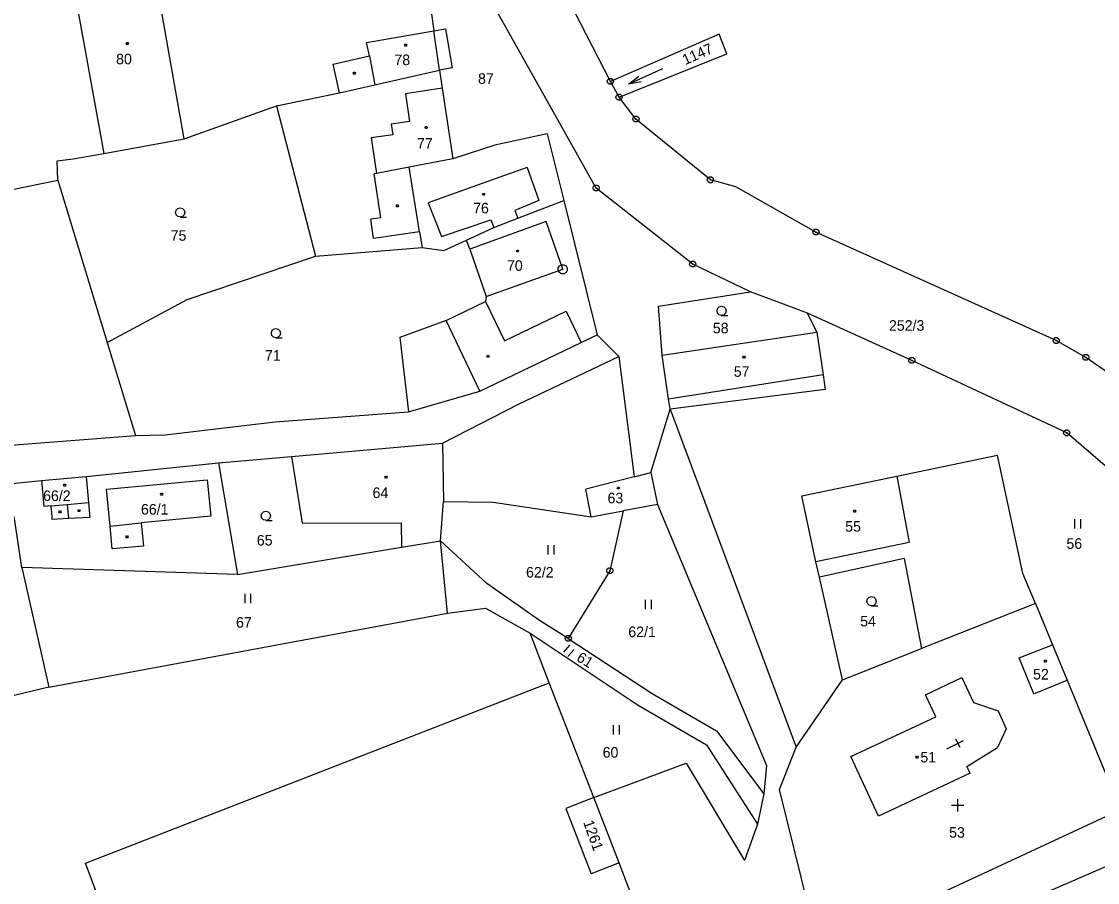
# Model space of a CAD drawing. Extents: x -812394 to -807601, y -1013098 to -1009266.
# Drawn here: x -809780.5 to -809607.5, y -1011042.4 to -1010903.9 of the extents above; entities that cross this region are included whole.
import ezdxf

# ---------------------------------------------------------------- set-up
doc = ezdxf.new("R2010")
doc.units = 0
for name, color, linetype in [('KN_HRANICE', 7, 'Continuous'), ('KN_KULTURY', 7, 'Continuous'), ('KN_MEZNIKY', 7, 'Continuous'), ('KN_PARCELY', 7, 'Continuous'), ('KN_SLUCKY', 7, 'Continuous')]:
    doc.layers.add(name, color=color, linetype=linetype)

# ---------------------------------------------------------------- blocks, each defined once
blk = doc.blocks.new('101')
blk.add_line((-0.05, 0), (0.05, 0))
blk.add_lwpolyline([(0.19, 0.72), (0.53, 0.53), (0.72, 0.19), (0.72, -0.2), (0.53, -0.54), (0.19, -0.73), (-0.2, -0.73), (-0.54, -0.54), (-0.73, -0.2), (-0.73, 0.19), (-0.54, 0.53), (-0.2, 0.72), (0.19, 0.72)])
blk = doc.blocks.new('304')
blk.add_lwpolyline([(0, 0), (-0.38, 0.1), (-0.65, 0.37), (-0.75, 0.74), (-0.65, 1.11), (-0.38, 1.38), (-0.01, 1.48), (0.36, 1.38), (0.63, 1.11), (0.73, 0.73), (0.63, 0.35), (0.36, 0.08), (-0.02, -0.02), (0.98, -0.02)])
blk = doc.blocks.new('306')
for p, q in [((-0.5, 1.5), (-0.5, 0)), ((0.5, 0), (0.5, 1.5))]:
    blk.add_line(p, q)
blk = doc.blocks.new('315')
for p, q in [((0, 0), (0, 2)), ((-1, 1), (1, 1))]:
    blk.add_line(p, q)
blk = doc.blocks.new('NAHRADNI_SYMBOL')
blk.add_lwpolyline([(0.09, 0.15), (0.18, 0), (0.09, -0.15), (-0.09, -0.15), (-0.18, 0), (-0.09, 0.15), (0.09, 0.15)])
blk = doc.blocks.new('802')
blk.add_line((-3, 0), (3, 0))
blk.add_lwpolyline([(1, 0.5), (3, 0), (1, -0.5)])
blk = doc.blocks.new('402')
blk.add_lwpolyline([(0.09, 0.15), (0.18, 0), (0.09, -0.15), (-0.09, -0.15), (-0.18, 0), (-0.09, 0.15), (0.09, 0.15)])
blk = doc.blocks.new('4091')
for p, q in [((0.75, 2), (-0.75, 2)), ((0, 0), (0, 3))]:
    blk.add_line(p, q)
blk = doc.blocks.new('105')
blk.add_line((-0.12, 0), (0.12, 0))
blk.add_lwpolyline([(0.15, 0.48), (0.4, 0.3), (0.5, 0.01), (0.4, -0.28), (0.15, -0.46), (-0.16, -0.46), (-0.41, -0.28), (-0.51, 0.01), (-0.41, 0.3), (-0.16, 0.48), (0.15, 0.48)])

msp = doc.modelspace()

# ---------------------------------------------------------------- linework, layer by layer
at = {"layer": 'KN_HRANICE'}
for p, q in [((-809754.39, -1010922.74), (-809759.51, -1010893.83)), ((-809772.62, -1010895.72), (-809767.28, -1010925.14)), ((-809715.33, -1010897.38), (-809714.24, -1010905.37)), ((-809688.11, -1010930.67), (-809707.45, -1010896.24)), ((-809685.82, -1010913.52), (-809691.58, -1010902.27)), ((-809725.07, -1010907.24), (-809714.24, -1010905.37)), ((-809714.24, -1010905.37), (-809712.36, -1010905.04)), ((-809712.36, -1010905.04), (-809711.25, -1010911.34)), ((-809724.57, -1010909.43), (-809725.07, -1010907.24)), ((-809730.42, -1010910.76), (-809724.57, -1010909.43)), ((-809729.38, -1010915.34), (-809730.42, -1010910.76)), ((-809723.69, -1010914.05), (-809713.3, -1010911.69)), ((-809711.25, -1010911.34), (-809713.3, -1010911.69)), ((-809713.3, -1010911.69), (-809712.87, -1010914.61)), ((-809684.42, -1010916.06), (-809685.82, -1010913.52)), ((-809729.38, -1010915.34), (-809723.69, -1010914.05)), ((-809712.87, -1010914.61), (-809711.14, -1010925.98)), ((-809739.53, -1010917.47), (-809729.38, -1010915.34)), ((-809681.71, -1010919.57), (-809684.42, -1010916.06)), ((-809754.39, -1010922.74), (-809739.53, -1010917.47)), ((-809739.53, -1010917.47), (-809733.26, -1010941.62)), ((-809669.73, -1010929.35), (-809681.71, -1010919.57)), ((-809695.97, -1010921.93), (-809704.43, -1010923.75)), ((-809695.97, -1010921.93), (-809693.3, -1010932.7)), ((-809767.28, -1010925.14), (-809754.39, -1010922.74)), ((-809704.43, -1010923.75), (-809711.14, -1010925.98)), ((-809772.22, -1010925.97), (-809767.28, -1010925.14)), ((-809774.81, -1010926.31), (-809772.22, -1010925.97)), ((-809774.68, -1010929.4), (-809774.81, -1010926.31)), ((-809711.14, -1010925.98), (-809718.2, -1010927.32)), ((-809716.52, -1010937.73), (-809718.2, -1010927.32)), ((-809810.23, -1010936.6), (-809774.68, -1010929.4)), ((-809774.68, -1010929.4), (-809766.75, -1010955.54)), ((-809672.58, -1010942.91), (-809688.11, -1010930.67)), ((-809665.64, -1010930.47), (-809669.73, -1010929.35)), ((-809652.76, -1010937.76), (-809665.64, -1010930.47)), ((-809700.73, -1010935.54), (-809693.3, -1010932.7)), ((-809693.3, -1010932.7), (-809687.95, -1010954.31)), ((-809704.57, -1010937), (-809700.73, -1010935.54)), ((-809716.52, -1010937.73), (-809716.12, -1010940.23)), ((-809708.99, -1010939.05), (-809704.57, -1010937)), ((-809712.62, -1010940.73), (-809708.99, -1010939.05)), ((-809708.43, -1010940.5), (-809708.99, -1010939.05)), ((-809614.11, -1010955.22), (-809652.76, -1010937.76)), ((-809733.26, -1010941.62), (-809716.12, -1010940.23)), ((-809716.12, -1010940.23), (-809712.62, -1010940.73)), ((-809708.43, -1010940.5), (-809705.79, -1010948.11)), ((-809753.89, -1010948.61), (-809733.26, -1010941.62)), ((-809663.31, -1010947.39), (-809672.58, -1010942.91)), ((-809705.79, -1010948.11), (-809705.9, -1010948.93)), ((-809678.08, -1010949.7), (-809663.31, -1010947.39)), ((-809654.15, -1010950.78), (-809663.31, -1010947.39)), ((-809766.75, -1010955.54), (-809753.89, -1010948.61)), ((-809712.21, -1010951.96), (-809705.9, -1010948.93)), ((-809677.51, -1010957.55), (-809678.08, -1010949.7)), ((-809637.34, -1010958.4), (-809654.15, -1010950.78)), ((-809652.62, -1010953.83), (-809654.15, -1010950.78)), ((-809712.21, -1010951.96), (-809719.69, -1010954.69)), ((-809719.69, -1010954.69), (-809718.32, -1010966.65)), ((-809690.53, -1010955.54), (-809687.95, -1010954.31)), ((-809687.95, -1010954.31), (-809684.45, -1010957.75)), ((-809677.51, -1010957.55), (-809652.62, -1010953.83)), ((-809652.62, -1010953.83), (-809651.63, -1010960.74)), ((-809766.75, -1010955.54), (-809762.22, -1010970.5)), ((-809706.83, -1010963.33), (-809690.53, -1010955.54)), ((-809609.36, -1010957.92), (-809614.11, -1010955.22)), ((-809700.5, -1010965.4), (-809684.45, -1010957.75)), ((-809684.45, -1010957.75), (-809682.01, -1010977.11)), ((-809676.47, -1010964.65), (-809677.51, -1010957.55)), ((-809612.44, -1010970.06), (-809637.34, -1010958.4)), ((-809605.9, -1010960.37), (-809609.36, -1010957.92)), ((-809651.63, -1010960.74), (-809651.3, -1010963.06)), ((-809718.32, -1010966.65), (-809706.83, -1010963.33)), ((-809651.3, -1010963.06), (-809676.23, -1010966.23)), ((-809712.82, -1010971.72), (-809700.5, -1010965.4)), ((-809676.23, -1010966.23), (-809676.47, -1010964.65)), ((-809739.76, -1010968.28), (-809718.32, -1010966.65)), ((-809679.34, -1010976.42), (-809676.23, -1010966.23)), ((-809676.23, -1010966.23), (-809655.96, -1011020.63)), ((-809757.42, -1010970.37), (-809739.76, -1010968.28)), ((-809785.75, -1010972.3), (-809762.22, -1010970.5)), ((-809762.22, -1010970.5), (-809757.42, -1010970.37)), ((-809599.93, -1010980.8), (-809612.44, -1010970.06)), ((-809737.1, -1010973.85), (-809712.82, -1010971.72)), ((-809712.82, -1010971.72), (-809712.69, -1010981.07)), ((-809748.85, -1010974.88), (-809737.1, -1010973.85)), ((-809737.1, -1010973.85), (-809735.37, -1010984.59)), ((-809639.78, -1010977.02), (-809623.55, -1010973.63)), ((-809619.47, -1010992.68), (-809623.55, -1010973.63)), ((-809770.14, -1010977.1), (-809748.85, -1010974.88)), ((-809748.85, -1010974.88), (-809745.78, -1010992.82)), ((-809777.31, -1010977.72), (-809770.14, -1010977.1)), ((-809770.14, -1010977.1), (-809769.76, -1010981.28)), ((-809682.01, -1010977.11), (-809679.34, -1010976.42)), ((-809679.34, -1010976.42), (-809678.26, -1010981.58)), ((-809655.06, -1010980.16), (-809639.78, -1010977.02)), ((-809782.57, -1010978.23), (-809777.31, -1010977.72)), ((-809777.31, -1010977.72), (-809776.92, -1010981.88)), ((-809652.76, -1010990.81), (-809655.06, -1010980.16)), ((-809775.78, -1010981.78), (-809776.92, -1010981.88)), ((-809775.61, -1010983.58), (-809775.78, -1010981.78)), ((-809769.76, -1010981.28), (-809769.54, -1010983.67)), ((-809713.13, -1010987.41), (-809712.69, -1010981.07)), ((-809712.69, -1010981.07), (-809704.69, -1010981.22)), ((-809704.69, -1010981.22), (-809688.94, -1010983.58)), ((-809688.94, -1010983.58), (-809683.77, -1010982.61)), ((-809683.77, -1010982.61), (-809685.91, -1010992.23)), ((-809678.26, -1010981.58), (-809683.77, -1010982.61)), ((-809678.26, -1010981.58), (-809660.72, -1011023.58)), ((-809780.48, -1010991.7), (-809781.71, -1010983.51)), ((-809775.59, -1010983.98), (-809775.61, -1010983.58)), ((-809772.99, -1010983.85), (-809775.59, -1010983.98)), ((-809769.54, -1010983.67), (-809772.99, -1010983.85)), ((-809735.37, -1010984.59), (-809719.45, -1010984.53)), ((-809719.45, -1010984.53), (-809719.41, -1010988.45)), ((-809719.41, -1010988.45), (-809713.13, -1010987.41)), ((-809712.03, -1010999.08), (-809713.13, -1010987.41)), ((-809705.68, -1010994.29), (-809713.13, -1010987.41)), ((-809745.78, -1010992.82), (-809719.41, -1010988.45)), ((-809652.21, -1010993.26), (-809652.76, -1010990.81)), ((-809638.59, -1010990.28), (-809652.21, -1010993.26)), ((-809638.59, -1010990.28), (-809635.78, -1011004.74)), ((-809780.48, -1010991.7), (-809776.12, -1011010.98)), ((-809745.78, -1010992.82), (-809780.48, -1010991.7)), ((-809685.91, -1010992.23), (-809692.6, -1011003.11)), ((-809617.47, -1010997.52), (-809619.47, -1010992.68)), ((-809697.2, -1011000.25), (-809705.68, -1010994.29)), ((-809648.52, -1011009.77), (-809652.21, -1010993.26)), ((-809712.03, -1010999.08), (-809705.9, -1010998.23)), ((-809705.9, -1010998.23), (-809698.74, -1011002.28)), ((-809617.47, -1010997.52), (-809635.78, -1011004.74)), ((-809617.47, -1010997.52), (-809614.74, -1011004.13)), ((-809776.12, -1011010.98), (-809712.03, -1010999.08)), ((-809692.6, -1011003.11), (-809697.2, -1011000.25)), ((-809695.65, -1011010.24), (-809698.74, -1011002.28)), ((-809698.74, -1011002.28), (-809681.36, -1011013.87)), ((-809692.6, -1011003.11), (-809679.1, -1011011.97)), ((-809648.52, -1011009.77), (-809635.78, -1011004.74)), ((-809620.06, -1011006.24), (-809614.74, -1011004.13)), ((-809614.74, -1011004.13), (-809612.38, -1011009.85)), ((-809617.75, -1011012.06), (-809620.06, -1011006.24)), ((-809770.25, -1011039.27), (-809695.65, -1011010.24)), ((-809688.47, -1011028.73), (-809695.65, -1011010.24)), ((-809655.96, -1011020.63), (-809648.52, -1011009.77)), ((-809635.16, -1011012.17), (-809629.28, -1011009.42)), ((-809629.28, -1011009.42), (-809627.41, -1011013.42)), ((-809617.75, -1011012.06), (-809612.38, -1011009.85)), ((-809612.38, -1011009.85), (-809603.78, -1011030.67)), ((-809776.12, -1011010.98), (-809797.21, -1011015.92)), ((-809679.1, -1011011.97), (-809668.78, -1011017.98)), ((-809681.36, -1011013.87), (-809670.36, -1011020.23)), ((-809633.51, -1011015.71), (-809635.16, -1011012.17)), ((-809627.41, -1011013.42), (-809623.47, -1011014.76)), ((-809623.47, -1011014.76), (-809622.19, -1011017.64)), ((-809647.18, -1011022.1), (-809633.51, -1011015.71)), ((-809668.78, -1011017.98), (-809661.16, -1011028.1)), ((-809622.19, -1011017.64), (-809623.55, -1011020.66)), ((-809670.36, -1011020.23), (-809662.17, -1011032.99)), ((-809658.63, -1011027.44), (-809655.96, -1011020.63)), ((-809628.49, -1011023.72), (-809623.55, -1011020.66)), ((-809642.69, -1011031.69), (-809647.18, -1011022.1)), ((-809688.47, -1011028.73), (-809673.64, -1011023.19)), ((-809673.64, -1011023.19), (-809664.28, -1011038.85)), ((-809660.72, -1011023.58), (-809661.16, -1011028.1)), ((-809627.98, -1011024.81), (-809628.49, -1011023.72)), ((-809627.98, -1011024.81), (-809642.69, -1011031.69)), ((-809652.22, -1011053.19), (-809658.63, -1011027.44)), ((-809688.47, -1011028.73), (-809692.99, -1011030.49)), ((-809684.4, -1011039.22), (-809688.47, -1011028.73)), ((-809661.16, -1011028.1), (-809662.17, -1011032.99)), ((-809638.37, -1011053.74), (-809581.58, -1011029.19)), ((-809692.99, -1011030.49), (-809688.92, -1011040.98)), ((-809603.78, -1011030.67), (-809652.22, -1011053.19)), ((-809662.17, -1011032.99), (-809664.28, -1011038.85)), ((-809752.49, -1011086.54), (-809770.25, -1011039.27)), ((-809684.4, -1011039.22), (-809688.92, -1011040.98)), ((-809677.42, -1011057.54), (-809684.4, -1011039.22))]:
    msp.add_line(p, q, dxfattribs=at)
msp.add_lwpolyline([(-809684.42, -1010916.06), (-809667.12, -1010909.09), (-809668.31, -1010905.92), (-809685.82, -1010913.52)], dxfattribs=at)
at = {"layer": 'KN_SLUCKY'}
for p, q in [((-809713.3, -1010911.69), (-809714.24, -1010905.37)), ((-809724.57, -1010909.43), (-809723.69, -1010914.05)), ((-809712.87, -1010914.61), (-809718.8, -1010915.51)), ((-809718.8, -1010915.51), (-809718.12, -1010919.96)), ((-809718.12, -1010919.96), (-809721.09, -1010920.41)), ((-809721.09, -1010920.41), (-809720.83, -1010922.09)), ((-809720.83, -1010922.09), (-809724.3, -1010922.62)), ((-809724.3, -1010922.62), (-809723.43, -1010928.32)), ((-809718.2, -1010927.32), (-809723.43, -1010928.32)), ((-809699.21, -1010927.36), (-809702.88, -1010928.67)), ((-809699.21, -1010927.36), (-809697.31, -1010932.7)), ((-809723.43, -1010928.32), (-809723.82, -1010928.4)), ((-809722.74, -1010935.45), (-809723.82, -1010928.4)), ((-809702.88, -1010928.67), (-809715.13, -1010933.03)), ((-809715.13, -1010933.03), (-809713, -1010938.48)), ((-809697.31, -1010932.7), (-809701.21, -1010934.27)), ((-809701.21, -1010934.27), (-809700.73, -1010935.54)), ((-809722.74, -1010935.45), (-809724.36, -1010935.68)), ((-809723.94, -1010938.79), (-809724.36, -1010935.68)), ((-809713, -1010938.48), (-809705.03, -1010935.8)), ((-809705.03, -1010935.8), (-809704.57, -1010937)), ((-809716.52, -1010937.73), (-809723.94, -1010938.79)), ((-809696.16, -1010936.04), (-809708.43, -1010940.5)), ((-809693.48, -1010943.7), (-809696.16, -1010936.04)), ((-809705.79, -1010948.11), (-809693.48, -1010943.7)), ((-809705.9, -1010948.93), (-809702.87, -1010955.24)), ((-809702.87, -1010955.24), (-809692.96, -1010950.48)), ((-809692.96, -1010950.48), (-809690.53, -1010955.54)), ((-809706.83, -1010963.33), (-809712.21, -1010951.96)), ((-809651.63, -1010960.74), (-809676.47, -1010964.65)), ((-809682.01, -1010977.11), (-809689.78, -1010979.12)), ((-809639.78, -1010977.02), (-809637.75, -1010987.67)), ((-809766.85, -1010979.12), (-809750.67, -1010977.62)), ((-809766.28, -1010985.05), (-809766.85, -1010979.12)), ((-809750.67, -1010977.62), (-809750.11, -1010983.48)), ((-809688.94, -1010983.58), (-809689.78, -1010979.12)), ((-809775.78, -1010981.78), (-809773.19, -1010981.57)), ((-809773.19, -1010981.57), (-809769.76, -1010981.28)), ((-809773.19, -1010981.57), (-809772.99, -1010983.85)), ((-809750.11, -1010983.48), (-809761.28, -1010984.55)), ((-809766.28, -1010985.05), (-809761.28, -1010984.55)), ((-809765.93, -1010988.73), (-809766.28, -1010985.05)), ((-809761.28, -1010984.55), (-809760.92, -1010988.26)), ((-809637.75, -1010987.67), (-809652.76, -1010990.81)), ((-809760.92, -1010988.26), (-809765.93, -1010988.73))]:
    msp.add_line(p, q, dxfattribs=at)

# ---------------------------------------------------------------- block references
at = {"layer": 'KN_KULTURY'}
for name, p in [('402', (-809763.5, -1010907.41)), ('402', (-809718.74, -1010907.68)), ('402', (-809726.99, -1010912.19)), ('402', (-809715.45, -1010920.92)), ('402', (-809706.19, -1010931.69)), ('304', (-809754.99, -1010935.33)), ('402', (-809720.08, -1010933.54)), ('402', (-809700.76, -1010940.79)), ('304', (-809667.93, -1010951.15)), ('304', (-809739.6, -1010954.76)), ('402', (-809705.51, -1010957.74)), ('402', (-809664.34, -1010957.87)), ('NAHRADNI_SYMBOL', (-809721.91, -1010977.18)), ('402', (-809773.58, -1010978.48)), ('402', (-809684.53, -1010978.92)), ('402', (-809757.99, -1010979.91)), ('402', (-809774.33, -1010982.77)), ('402', (-809771.29, -1010982.58)), ('304', (-809741.22, -1010984.12)), ('402', (-809646.54, -1010982.66)), ('306', (-809610.68, -1010985.44)), ('402', (-809763.57, -1010986.79)), ('306', (-809695.36, -1010989.6)), ('306', (-809744.14, -1010997.47)), ('304', (-809643.82, -1010997.88)), ('306', (-809679.74, -1010998.4)), ('402', (-809615.86, -1011006.77)), ('306', (-809684.86, -1011018.57)), ('402', (-809636.51, -1011022.21)), ('315', (-809629.96, -1011030.96))]:
    msp.add_blockref(name, p, dxfattribs=at)
for name, p, rotation in [('802', (-809680.16, -1010912.72), -155.74054600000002), ('306', (-809693.02, -1011005.67), -42.294903), ('4091', (-809631.72, -1011020.9), -63.43704500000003)]:
    msp.add_blockref(name, p, dxfattribs=dict(at, rotation=rotation))
at = {"layer": 'KN_MEZNIKY'}
for name, p in [('105', (-809685.82, -1010913.52)), ('105', (-809684.42, -1010916.06)), ('105', (-809681.71, -1010919.57)), ('105', (-809669.73, -1010929.35)), ('105', (-809688.11, -1010930.67)), ('105', (-809652.76, -1010937.76)), ('105', (-809672.58, -1010942.91)), ('101', (-809693.48, -1010943.72)), ('105', (-809614.11, -1010955.22)), ('105', (-809637.34, -1010958.4)), ('105', (-809609.36, -1010957.92)), ('105', (-809612.44, -1010970.06)), ('105', (-809685.91, -1010992.23)), ('105', (-809692.6, -1011003.11))]:
    msp.add_blockref(name, p, dxfattribs=at)

# ---------------------------------------------------------------- texts
at = {"layer": 'KN_PARCELY'}
for s, rotation, p in [('1147', 23.892, (-809673.8, -1010910.92)), ('61', 328.362, (-809691.4, -1011006.63)), ('1261', 289.745, (-809690.22, -1011032.7))]:
    msp.add_text(s, height=1.7, rotation=rotation, dxfattribs=at).set_placement(p)
for s, p in [('80', (-809765.32, -1010910.77)), ('78', (-809720.56, -1010910.9)), ('87', (-809707.11, -1010913.91)), ('77', (-809716.93, -1010924.34)), ('76', (-809707.9, -1010934.75)), ('75', (-809756.54, -1010939.15)), ('70', (-809702.45, -1010943.99)), ('58', (-809669.35, -1010954.04)), ('252/3', (-809641.02, -1010953.63)), ('71', (-809741.38, -1010958.44)), ('57', (-809665.98, -1010961.04)), ('66/2', (-809777.06, -1010981.02)), ('64', (-809724.07, -1010980.54)), ('63', (-809686.29, -1010981.39)), ('66/1', (-809761.32, -1010983.2)), ('55', (-809648.06, -1010985.95)), ('65', (-809742.69, -1010988.18)), ('56', (-809612.48, -1010988.71)), ('62/2', (-809699.39, -1010993.33)), ('67', (-809746.03, -1011001.4)), ('54', (-809645.65, -1011001.19)), ('62/1', (-809682.94, -1011002.91)), ('52', (-809617.85, -1011009.73)), ('60', (-809687.07, -1011022.3)), ('51', (-809635.97, -1011023.07)), ('53', (-809631.35, -1011035.18))]:
    msp.add_text(s, height=1.7, dxfattribs=at).set_placement(p)

doc.saveas('drawing.dxf')
